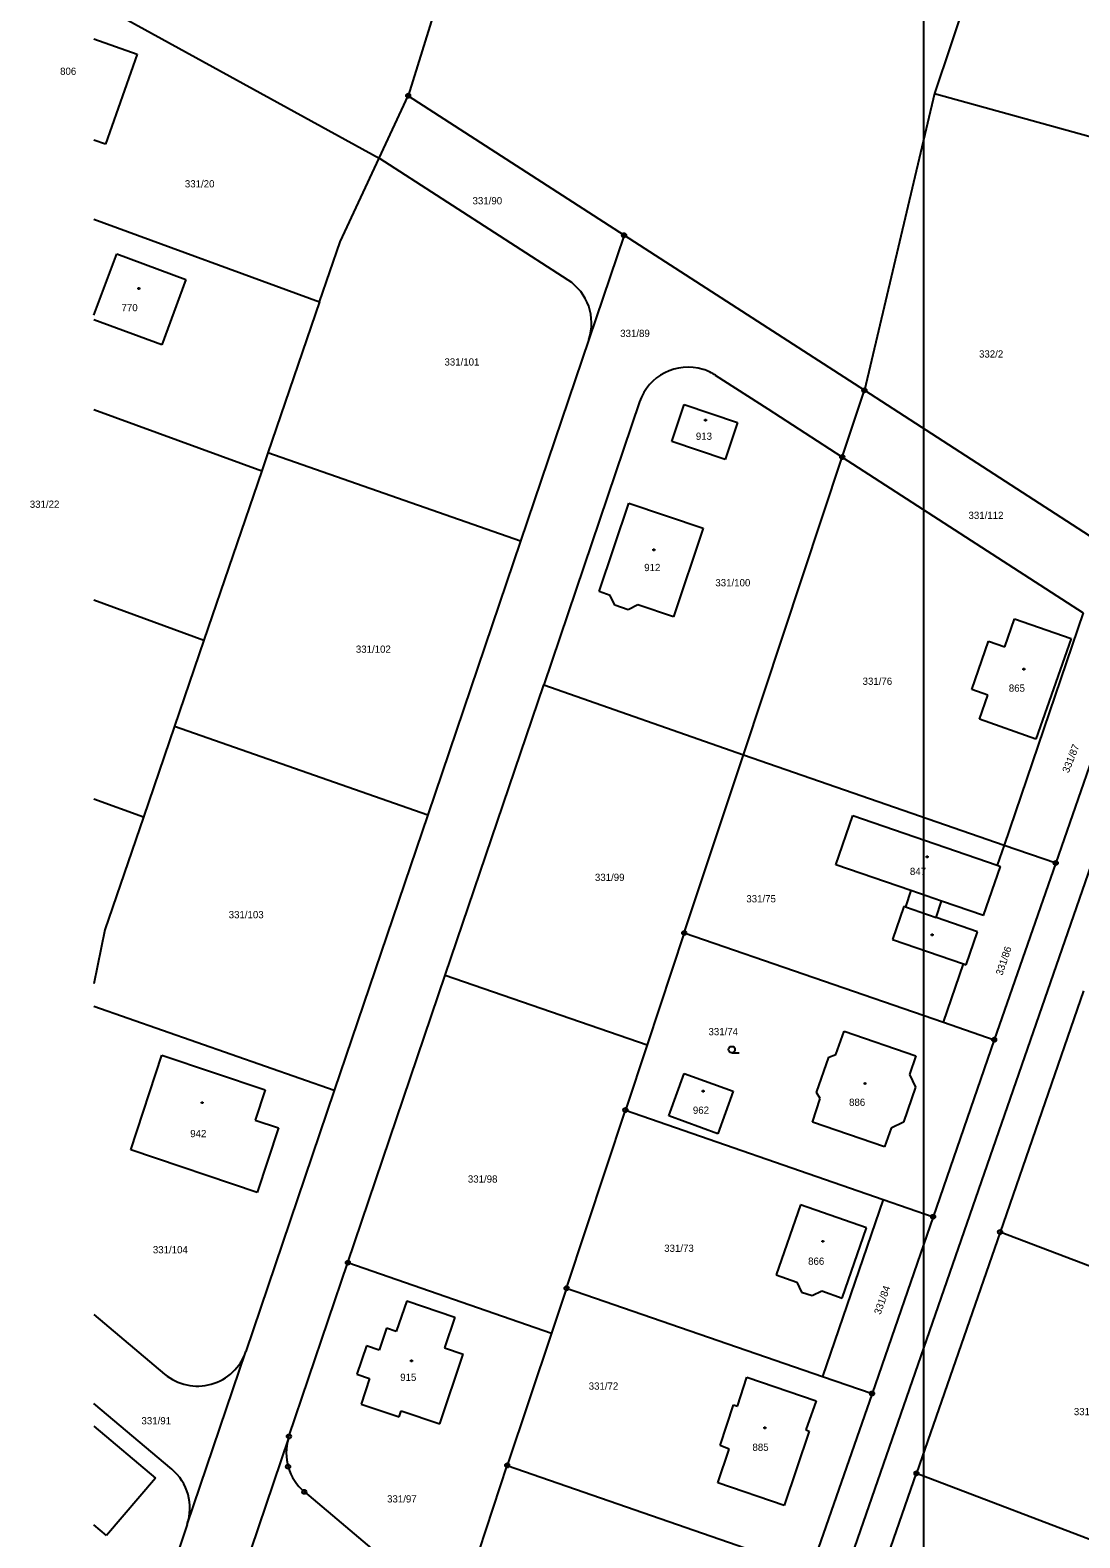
# Model space of a CAD drawing. Extents: x -770973 to -770265, y -1049936 to -1049427.
# Drawn here: x -770963.6 to -770840.3, y -1049695.4 to -1049518.2 of the extents above; entities that cross this region are included whole.
import ezdxf

# ---------------------------------------------------------------- set-up
doc = ezdxf.new("R2010")
doc.units = 0
for name, color, linetype in [('Vrstva 1', 7, 'Continuous'), ('Vrstva 14', 7, 'Continuous'), ('Vrstva 15', 7, 'Continuous'), ('Vrstva 2', 7, 'Continuous'), ('Vrstva 23', 7, 'Continuous'), ('Vrstva 25', 7, 'Continuous'), ('Vrstva 28', 7, 'Continuous'), ('Vrstva 30', 7, 'Continuous'), ('Vrstva 63', 7, 'Continuous')]:
    doc.layers.add(name, color=color, linetype=linetype)

msp = doc.modelspace()

# ---------------------------------------------------------------- linework, layer by layer
at = {"layer": 'Vrstva 1'}
for p, q in [((-770837.69, -1049466.63), (-770857.36, -1049525.64)), ((-770911.15, -1049499.99), (-770919.21, -1049525.91)), ((-770956.13, -1049514.84), (-770922.63, -1049533.23)), ((-770956.13, -1049519.21), (-770951.04, -1049521.03)), ((-770951.04, -1049521.03), (-770954.77, -1049531.59)), ((-770922.63, -1049533.23), (-770919.21, -1049525.91)), ((-770919.21, -1049525.91), (-770893.84, -1049542.3)), ((-770857.36, -1049525.64), (-770865.61, -1049560.53)), ((-770857.36, -1049525.64), (-770827.33, -1049533.95)), ((-770954.77, -1049531.59), (-770956.13, -1049531.11)), ((-770927.22, -1049543.06), (-770922.63, -1049533.23)), ((-770900.42, -1049547.58), (-770922.63, -1049533.23)), ((-770956.13, -1049540.42), (-770929.63, -1049550.13)), ((-770929.63, -1049550.13), (-770927.22, -1049543.06)), ((-770893.84, -1049542.3), (-770897.99, -1049554.54)), ((-770893.84, -1049542.3), (-770865.61, -1049560.53)), ((-770956.13, -1049551.68), (-770953.46, -1049544.49)), ((-770953.46, -1049544.49), (-770945.33, -1049547.51)), ((-770945.33, -1049547.51), (-770948.17, -1049555.17)), ((-770929.63, -1049550.13), (-770935.69, -1049567.88)), ((-770948.17, -1049555.17), (-770956.13, -1049552.23)), ((-770897.99, -1049554.54), (-770906.03, -1049578.27)), ((-770876.92, -1049562.75), (-770883.09, -1049558.77)), ((-770868.21, -1049568.38), (-770865.61, -1049560.53)), ((-770865.61, -1049560.53), (-770837.22, -1049578.87)), ((-770956.13, -1049562.78), (-770936.42, -1049570.01)), ((-770892.03, -1049561.88), (-770903.29, -1049595.14)), ((-770888.22, -1049566.55), (-770886.77, -1049562.18)), ((-770886.77, -1049562.18), (-770880.5, -1049564.31)), ((-770868.21, -1049568.38), (-770876.92, -1049562.75)), ((-770880.5, -1049564.31), (-770881.96, -1049568.65)), ((-770881.96, -1049568.65), (-770888.22, -1049566.55)), ((-770935.69, -1049567.88), (-770936.42, -1049570.01)), ((-770906.03, -1049578.27), (-770935.69, -1049567.88)), ((-770879.81, -1049603.37), (-770868.21, -1049568.38)), ((-770868.21, -1049568.38), (-770839.89, -1049586.69)), ((-770936.42, -1049570.01), (-770943.21, -1049589.88)), ((-770896.77, -1049584.19), (-770893.29, -1049573.8)), ((-770893.29, -1049573.8), (-770884.54, -1049576.75)), ((-770884.54, -1049576.75), (-770888.05, -1049587.17)), ((-770906.03, -1049578.27), (-770916.92, -1049610.44)), ((-770895.49, -1049584.63), (-770896.77, -1049584.19)), ((-770956.13, -1049585.14), (-770943.21, -1049589.88)), ((-770894.92, -1049585.79), (-770895.49, -1049584.63)), ((-770893.37, -1049586.32), (-770894.92, -1049585.79)), ((-770892.24, -1049585.73), (-770893.37, -1049586.32)), ((-770888.05, -1049587.17), (-770892.24, -1049585.73)), ((-770839.89, -1049586.69), (-770849.2, -1049613.98)), ((-770849.11, -1049590.68), (-770847.97, -1049587.38)), ((-770847.97, -1049587.38), (-770841.32, -1049589.69)), ((-770841.32, -1049589.69), (-770845.47, -1049601.53)), ((-770943.21, -1049589.88), (-770946.66, -1049600.01)), ((-770852.98, -1049595.7), (-770851.01, -1049590.02)), ((-770851.01, -1049590.02), (-770849.11, -1049590.68)), ((-770895.53, -1049779.65), (-770830.75, -1049592.61)), ((-770835.64, -1049594.46), (-770843.13, -1049616.09)), ((-770914.85, -1049629.26), (-770903.29, -1049595.14)), ((-770903.29, -1049595.14), (-770879.81, -1049603.37)), ((-770851.1, -1049596.37), (-770852.98, -1049595.7)), ((-770852.09, -1049599.2), (-770851.1, -1049596.37)), ((-770946.66, -1049600.01), (-770950.31, -1049610.71)), ((-770946.66, -1049600.01), (-770916.92, -1049610.44)), ((-770845.47, -1049601.53), (-770852.09, -1049599.2)), ((-770886.77, -1049624.32), (-770879.81, -1049603.37)), ((-770879.81, -1049603.37), (-770849.2, -1049613.98)), ((-770950.31, -1049610.71), (-770956.13, -1049608.57)), ((-770950.31, -1049610.71), (-770954.86, -1049623.95)), ((-770916.92, -1049610.44), (-770927.9, -1049642.85)), ((-770868.97, -1049616.3), (-770866.96, -1049610.49)), ((-770866.96, -1049610.49), (-770850.01, -1049616.36)), ((-770849.2, -1049613.98), (-770850.01, -1049616.36)), ((-770849.2, -1049613.98), (-770843.13, -1049616.09)), ((-770860.16, -1049619.34), (-770868.97, -1049616.3)), ((-770843.13, -1049616.09), (-770850.36, -1049636.87)), ((-770851.62, -1049622.28), (-770849.62, -1049616.5)), ((-770850.01, -1049616.36), (-770849.62, -1049616.5)), ((-770860.16, -1049619.34), (-770860.77, -1049621.25)), ((-770860.96, -1049621.2), (-770862.3, -1049625.1)), ((-770860.77, -1049621.25), (-770860.96, -1049621.2)), ((-770857.18, -1049622.48), (-770856.56, -1049620.59)), ((-770851.62, -1049622.28), (-770856.56, -1049620.59)), ((-770852.3, -1049624.17), (-770857.18, -1049622.48)), ((-770954.86, -1049623.95), (-770956.13, -1049630.3)), ((-770886.77, -1049624.32), (-770891.14, -1049637.48)), ((-770886.77, -1049624.32), (-770856.31, -1049634.82)), ((-770862.3, -1049625.1), (-770853.97, -1049627.96)), ((-770853.64, -1049628.07), (-770852.3, -1049624.17)), ((-770856.31, -1049634.82), (-770853.97, -1049627.96)), ((-770853.97, -1049627.96), (-770853.64, -1049628.07)), ((-770926.3, -1049663.07), (-770914.85, -1049629.26)), ((-770914.85, -1049629.26), (-770891.14, -1049637.48)), ((-770839.87, -1049631.13), (-770849.67, -1049659.48)), ((-770927.9, -1049642.85), (-770956.13, -1049632.95)), ((-770856.31, -1049634.82), (-770850.36, -1049636.87)), ((-770891.14, -1049637.48), (-770893.69, -1049645.14)), ((-770868.95, -1049638.61), (-770868, -1049635.84)), ((-770868, -1049635.84), (-770859.56, -1049638.77)), ((-770850.36, -1049636.87), (-770857.53, -1049657.68)), ((-770951.81, -1049649.82), (-770948.14, -1049638.68)), ((-770948.14, -1049638.68), (-770936.02, -1049642.77)), ((-770871.22, -1049643.05), (-770869.79, -1049638.92)), ((-770869.79, -1049638.92), (-770868.95, -1049638.61)), ((-770859.56, -1049638.77), (-770860.32, -1049640.97)), ((-770888.58, -1049645.82), (-770886.79, -1049640.85)), ((-770886.79, -1049640.85), (-770881.02, -1049642.92)), ((-770860.32, -1049640.97), (-770859.6, -1049642.44)), ((-770927.9, -1049642.85), (-770938.28, -1049673.51)), ((-770936.02, -1049642.77), (-770937.18, -1049646.32)), ((-770859.6, -1049642.44), (-770861.01, -1049646.57)), ((-770881.02, -1049642.92), (-770882.81, -1049647.92)), ((-770871.7, -1049646.55), (-770870.79, -1049643.78)), ((-770870.79, -1049643.78), (-770871.22, -1049643.05)), ((-770937.18, -1049646.32), (-770934.44, -1049647.21)), ((-770900.6, -1049666.08), (-770893.69, -1049645.14)), ((-770893.69, -1049645.14), (-770863.42, -1049655.64)), ((-770882.81, -1049647.92), (-770888.58, -1049645.82)), ((-770934.44, -1049647.21), (-770936.96, -1049654.81)), ((-770863.24, -1049649.47), (-770871.7, -1049646.55)), ((-770862.46, -1049647.27), (-770863.24, -1049649.47)), ((-770861.01, -1049646.57), (-770862.46, -1049647.27)), ((-770936.96, -1049654.81), (-770951.81, -1049649.82)), ((-770873.12, -1049656.28), (-770875.99, -1049664.51)), ((-770865.36, -1049658.97), (-770873.12, -1049656.28)), ((-770863.42, -1049655.64), (-770870.52, -1049676.45)), ((-770863.42, -1049655.64), (-770857.53, -1049657.68)), ((-770857.53, -1049657.68), (-770864.71, -1049678.45)), ((-770868.21, -1049667.23), (-770865.36, -1049658.97)), ((-770849.67, -1049659.48), (-770859.49, -1049687.83)), ((-770817.97, -1049671.55), (-770849.67, -1049659.48)), ((-770933.22, -1049683.5), (-770926.3, -1049663.07)), ((-770926.3, -1049663.07), (-770902.37, -1049671.37)), ((-770875.99, -1049664.51), (-770873.55, -1049665.37)), ((-770873.55, -1049665.37), (-770873, -1049666.52)), ((-770919.38, -1049667.56), (-770920.61, -1049671.17)), ((-770919.38, -1049667.56), (-770913.72, -1049669.48)), ((-770900.6, -1049666.08), (-770902.37, -1049671.37)), ((-770900.6, -1049666.08), (-770870.52, -1049676.45)), ((-770873, -1049666.52), (-770871.75, -1049666.93)), ((-770871.75, -1049666.93), (-770870.62, -1049666.39)), ((-770870.62, -1049666.39), (-770868.21, -1049667.23)), ((-770956.13, -1049669.15), (-770947.83, -1049676.17)), ((-770921.74, -1049670.79), (-770922.61, -1049673.35)), ((-770920.61, -1049671.17), (-770921.74, -1049670.79)), ((-770913.72, -1049669.48), (-770914.93, -1049673.07)), ((-770924.12, -1049672.84), (-770925.25, -1049676.16)), ((-770922.61, -1049673.35), (-770924.12, -1049672.84)), ((-770902.37, -1049671.37), (-770907.58, -1049686.9)), ((-770945.18, -1049693.85), (-770938.28, -1049673.51)), ((-770915.51, -1049682.01), (-770912.76, -1049673.81)), ((-770914.93, -1049673.07), (-770912.76, -1049673.81)), ((-770925.25, -1049676.16), (-770923.75, -1049676.67)), ((-770880.51, -1049679.93), (-770879.41, -1049676.52)), ((-770879.41, -1049676.52), (-770871.28, -1049679.3)), ((-770870.52, -1049676.45), (-770864.71, -1049678.45)), ((-770923.75, -1049676.67), (-770924.75, -1049679.7)), ((-770946.99, -1049687.34), (-770956.13, -1049679.64)), ((-770924.75, -1049679.7), (-770920.28, -1049681.21)), ((-770882.57, -1049684.57), (-770881, -1049679.77)), ((-770881, -1049679.77), (-770880.51, -1049679.93)), ((-770871.28, -1049679.3), (-770872.49, -1049682.71)), ((-770864.71, -1049678.45), (-770871.93, -1049699.25)), ((-770920.28, -1049681.21), (-770920.04, -1049680.5)), ((-770920.04, -1049680.5), (-770915.51, -1049682.01)), ((-770956.13, -1049682.28), (-770948.91, -1049688.41)), ((-770933.28, -1049683.69), (-770933.22, -1049683.5)), ((-770872.09, -1049682.86), (-770875.04, -1049691.6)), ((-770872.49, -1049682.71), (-770872.09, -1049682.86)), ((-770933.28, -1049683.69), (-770939.97, -1049703.48)), ((-770882.81, -1049688.95), (-770881.49, -1049685)), ((-770881.49, -1049685), (-770882.57, -1049684.57)), ((-770913.56, -1049705.05), (-770907.58, -1049686.9)), ((-770907.58, -1049686.9), (-770877.62, -1049697.28)), ((-770948.91, -1049688.41), (-770954.65, -1049695.16)), ((-770875.04, -1049691.6), (-770882.81, -1049688.95)), ((-770869.31, -1049716.19), (-770859.49, -1049687.83)), ((-770859.49, -1049687.83), (-770828.17, -1049699.74)), ((-770931.41, -1049690.01), (-770913.56, -1049705.05)), ((-770954.65, -1049695.16), (-770956.13, -1049693.9)), ((-770945.18, -1049693.85), (-770952.05, -1049714.16))]:
    msp.add_line(p, q, dxfattribs=at)
for centre, radius, start, end in [((-770903.67, -1049552.62), 6, 341.3165, 57.1755), ((-770886.35, -1049563.8), 5.99, 72.6795, 161.3076), ((-770886.23, -1049563.58), 5.75, 56.8355, 73.1731), ((-770943.96, -1049671.58), 6, 229.9037, 341.2249), ((-770927.56, -1049685.43), 5.98, 163.0537, 229.9118), ((-770950.86, -1049691.92), 6, 341.2576, 49.8178)]:
    msp.add_arc(centre, radius, start, end, dxfattribs=at)
at = {"layer": 'Vrstva 2'}
for p, q in [((-770856.56, -1049620.59), (-770860.16, -1049619.34)), ((-770860.77, -1049621.25), (-770857.18, -1049622.48))]:
    msp.add_line(p, q, dxfattribs=at)
at = {"layer": 'Vrstva 23'}
msp.add_line((-770881.19, -1049638.4), (-770880.31, -1049638.4), dxfattribs=at)
msp.add_circle((-770881.19, -1049638.02), 0.375, dxfattribs=at)
at = {"layer": 'Vrstva 25'}
for p, q in [((-770950.95, -1049548.48), (-770950.8, -1049548.48)), ((-770950.95, -1049548.63), (-770950.95, -1049548.48)), ((-770950.8, -1049548.63), (-770950.95, -1049548.63)), ((-770950.8, -1049548.48), (-770950.8, -1049548.63)), ((-770884.34, -1049563.97), (-770884.19, -1049563.97)), ((-770884.34, -1049564.12), (-770884.34, -1049563.97)), ((-770884.19, -1049564.12), (-770884.34, -1049564.12)), ((-770884.19, -1049563.97), (-770884.19, -1049564.12)), ((-770890.42, -1049579.21), (-770890.27, -1049579.21)), ((-770890.42, -1049579.36), (-770890.42, -1049579.21)), ((-770890.27, -1049579.36), (-770890.42, -1049579.36)), ((-770890.27, -1049579.21), (-770890.27, -1049579.36)), ((-770846.96, -1049593.22), (-770846.81, -1049593.22)), ((-770846.96, -1049593.37), (-770846.96, -1049593.22)), ((-770846.81, -1049593.22), (-770846.81, -1049593.37)), ((-770846.81, -1049593.37), (-770846.96, -1049593.37)), ((-770858.3, -1049615.3), (-770858.15, -1049615.3)), ((-770858.3, -1049615.45), (-770858.3, -1049615.3)), ((-770858.15, -1049615.45), (-770858.3, -1049615.45)), ((-770858.15, -1049615.3), (-770858.15, -1049615.45)), ((-770857.71, -1049624.46), (-770857.56, -1049624.46)), ((-770857.71, -1049624.61), (-770857.71, -1049624.46)), ((-770857.56, -1049624.61), (-770857.71, -1049624.61)), ((-770857.56, -1049624.46), (-770857.56, -1049624.61)), ((-770884.62, -1049642.85), (-770884.47, -1049642.85)), ((-770884.62, -1049643), (-770884.62, -1049642.85)), ((-770884.47, -1049642.85), (-770884.47, -1049643)), ((-770865.61, -1049641.94), (-770865.46, -1049641.94)), ((-770865.61, -1049642.09), (-770865.61, -1049641.94)), ((-770865.46, -1049642.09), (-770865.61, -1049642.09)), ((-770865.46, -1049641.94), (-770865.46, -1049642.09)), ((-770943.48, -1049644.19), (-770943.33, -1049644.19)), ((-770943.48, -1049644.34), (-770943.48, -1049644.19)), ((-770943.33, -1049644.34), (-770943.48, -1049644.34)), ((-770943.33, -1049644.19), (-770943.33, -1049644.34)), ((-770884.47, -1049643), (-770884.62, -1049643)), ((-770870.57, -1049660.49), (-770870.42, -1049660.49)), ((-770870.57, -1049660.64), (-770870.57, -1049660.49)), ((-770870.42, -1049660.49), (-770870.42, -1049660.64)), ((-770870.42, -1049660.64), (-770870.57, -1049660.64)), ((-770918.9, -1049674.53), (-770918.75, -1049674.53)), ((-770918.9, -1049674.68), (-770918.9, -1049674.53)), ((-770918.75, -1049674.68), (-770918.9, -1049674.68)), ((-770918.75, -1049674.53), (-770918.75, -1049674.68)), ((-770877.37, -1049682.42), (-770877.22, -1049682.42)), ((-770877.37, -1049682.57), (-770877.37, -1049682.42)), ((-770877.22, -1049682.57), (-770877.37, -1049682.57)), ((-770877.22, -1049682.42), (-770877.22, -1049682.57))]:
    msp.add_line(p, q, dxfattribs=at)
at = {"layer": 'Vrstva 28'}
for centre, radius in [((-770919.21, -1049525.91), 0.25), ((-770919.21, -1049525.91), 0.005), ((-770893.84, -1049542.3), 0.25), ((-770893.84, -1049542.3), 0.005), ((-770865.61, -1049560.53), 0.25), ((-770865.61, -1049560.53), 0.005), ((-770868.21, -1049568.38), 0.25), ((-770868.21, -1049568.38), 0.005), ((-770843.13, -1049616.09), 0.25), ((-770843.13, -1049616.09), 0.005), ((-770886.77, -1049624.32), 0.25), ((-770886.77, -1049624.32), 0.005), ((-770850.36, -1049636.87), 0.25), ((-770850.36, -1049636.87), 0.005), ((-770893.69, -1049645.14), 0.25), ((-770893.69, -1049645.14), 0.005), ((-770857.53, -1049657.68), 0.25), ((-770857.53, -1049657.68), 0.005), ((-770849.67, -1049659.48), 0.25), ((-770849.67, -1049659.48), 0.005), ((-770926.3, -1049663.07), 0.25), ((-770926.3, -1049663.07), 0.005), ((-770900.6, -1049666.08), 0.25), ((-770900.6, -1049666.08), 0.005), ((-770864.71, -1049678.45), 0.25), ((-770864.71, -1049678.45), 0.005), ((-770933.22, -1049683.5), 0.25), ((-770933.22, -1049683.5), 0.005), ((-770933.32, -1049687.04), 0.25), ((-770933.32, -1049687.04), 0.005), ((-770907.58, -1049686.9), 0.25), ((-770907.58, -1049686.9), 0.005), ((-770859.49, -1049687.83), 0.25), ((-770859.49, -1049687.83), 0.005), ((-770931.41, -1049690.01), 0.25), ((-770931.41, -1049690.01), 0.005)]:
    msp.add_circle(centre, radius, dxfattribs=at)
at = {"layer": 'Vrstva 30'}
msp.add_arc((-770886.23, -1049563.58), 5.75, 56.8355, 73.1731, dxfattribs=at)
at = {"layer": 'Vrstva 63'}
msp.add_lwpolyline([(-770858.67, -1049892.7), (-770264.67, -1049892.7), (-770264.67, -1049472.7), (-770858.67, -1049472.7), (-770858.67, -1049892.7)], dxfattribs=at)

# ---------------------------------------------------------------- texts
at = {"layer": 'Vrstva 14'}
for s, p in [('331/20', (-770945.45, -1049536.68)), ('331/90', (-770911.65, -1049538.67)), ('331/89', (-770894.3, -1049554.26)), ('332/2', (-770852.14, -1049556.68)), ('331/101', (-770914.95, -1049557.62)), ('331/22', (-770963.67, -1049574.34)), ('331/112', (-770853.38, -1049575.65)), ('331/100', (-770883.12, -1049583.57)), ('331/102', (-770925.36, -1049591.38)), ('331/76', (-770865.82, -1049595.15)), ('331/99', (-770897.27, -1049618.2)), ('331/75', (-770879.48, -1049620.72)), ('331/103', (-770940.3, -1049622.59)), ('331/74', (-770883.93, -1049636.34)), ('331/98', (-770912.2, -1049653.66)), ('331/104', (-770949.21, -1049661.97)), ('331/73', (-770889.13, -1049661.8)), ('331/72', (-770898, -1049678)), ('331/58', (-770841, -1049681)), ('331/91', (-770950.55, -1049682.08)), ('331/97', (-770921.69, -1049691.26))]:
    msp.add_text(s, height=0.85, dxfattribs=at).set_placement(p)
for s, rotation, p in [('331/87', 68.421, (-770841.61, -1049605.57)), ('331/86', 71.5367, (-770849.4, -1049629.37)), ('331/84', 70.518, (-770863.71, -1049669.24))]:
    msp.add_text(s, height=0.85, rotation=rotation, dxfattribs=at).set_placement(p)
at = {"layer": 'Vrstva 15'}
for s, p in [('806', (-770960.11, -1049523.45)), ('770', (-770952.89, -1049551.23)), ('913', (-770885.41, -1049566.35)), ('912', (-770891.48, -1049581.78)), ('865', (-770848.64, -1049595.96)), ('847', (-770860.26, -1049617.5)), ('886', (-770867.41, -1049644.64)), ('962', (-770885.76, -1049645.57)), ('942', (-770944.82, -1049648.32)), ('866', (-770872.22, -1049663.32)), ('915', (-770920.15, -1049676.97)), ('885', (-770878.76, -1049685.19))]:
    msp.add_text(s, height=0.85, dxfattribs=at).set_placement(p)

doc.saveas('drawing.dxf')
